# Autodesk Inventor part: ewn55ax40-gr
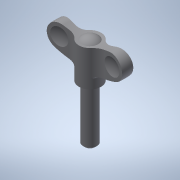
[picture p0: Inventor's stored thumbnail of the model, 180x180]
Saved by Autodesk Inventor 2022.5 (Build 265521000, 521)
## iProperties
Created: 2016-12
Part Number: ewn55ax40-gr
Material: 一般
Document SubType Name: Modeling
Designer: imaocorp
Density: 1 g/cm^3
Appearance: 既定
Author: imaocorp
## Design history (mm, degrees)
node "ewn55ax40-gr.x_t1"
node "ewn55ax40-gr"
node "Base1"
